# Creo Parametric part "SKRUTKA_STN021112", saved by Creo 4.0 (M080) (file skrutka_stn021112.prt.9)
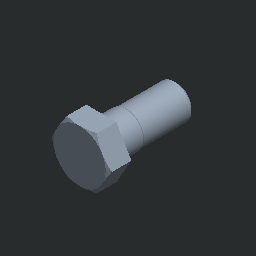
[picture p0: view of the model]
Units: millimeter Kilogram Sec (mmKs); MM, KILOGRAM, SECS
Materials in the file: OCEL_N

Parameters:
  MFG_WP_MATERIAL = "OCEL"
  NAZOV = "SKRUTKA_STN021112"
  NORMA = "STN 02 1112"
  PTC_MATERIAL_NAME = "OCEL_N"

Other parameters: HMOTNOST, HUSTOTA, D10, D25, D23, D15

Created from: C021112.PRT

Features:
  1. datum plane "DTM1"
  2. protrusion
  3. datum plane "DTM2"
  4. cut
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
Other named items: BLIND

Layers: 1, 2, 3, 4, 5, 6, 7, 8, 9, 10, 11, 12, 13, 14, 15, 16, 17, 18, 19, 20, 21, 22, 23, 24, 25, 26, 27, 28, 29, 30, 31, 32

Family table entries: GENERIC, SKRUTKA_M10, SKRUTKA_STN021112, value(d_val), 2/&, 2/0, value(i_val), SKRUTKA_M12, SKRUTKA_STN021112, !/(, 2/*, 2/ , 2/2, SKRUTKA_M14, SKRUTKA_STN021112, !/,, 2/., 2/", 2/5, SKRUTKA_M16, SKRUTKA_STN021112, !/0, 2/1, 2/$, 2/8, SKRUTKA_M18, SKRUTKA_STN021112, !/2, 2/3, 2/(, 2/;, SKRUTKA_M20, SKRUTKA_STN021112, !/4, 2/5, 2/*, 2/>, SKRUTKA_M22, SKRUTKA_STN021112, !/6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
